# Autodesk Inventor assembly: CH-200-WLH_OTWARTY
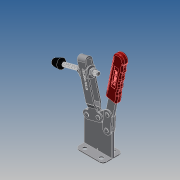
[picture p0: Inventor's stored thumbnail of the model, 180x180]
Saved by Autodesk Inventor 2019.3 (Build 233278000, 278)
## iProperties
Company: Î¢ÈíÖÐ¹ú
Created: 2011-05
Part Number: CH-200-WLH_OTWARTY
Material: Ogólny
Description: STEP AP203
Document SubType Name: Assembly
Designer: CADENGINEERING4
Sending System: SolidWorks 2010
Preprocessor: SwSTEP 2.0
Title: CH-200-WLH.STEP
Author: Î¢ÈíÓÃ»§
Revision Number: ÈÎºÎ
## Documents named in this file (10)
- E:\STRONA\Horizontal toggle clamp\CH-200-WLH\CH-200-WLH_OTWARTY.iam
- E:\STRONA\Horizontal toggle clamp\CH-200-WLH\FW380.ipt
- E:\STRONA\Horizontal toggle clamp\CH-200-WLH\200-W-05.ipt
- E:\STRONA\Horizontal toggle clamp\CH-200-WLH\38312-01.ipt
- E:\STRONA\Horizontal toggle clamp\CH-200-WLH\200-W-04.ipt
- E:\STRONA\Horizontal toggle clamp\CH-200-WLH\200-WLH-01.ipt
- E:\STRONA\Horizontal toggle clamp\CH-200-WLH\200-W-03.ipt
- E:\STRONA\Horizontal toggle clamp\CH-200-WLH\200-WLH-02.ipt
- E:\STRONA\Horizontal toggle clamp\CH-200-WLH\200-W-06.ipt
- E:\STRONA\Horizontal toggle clamp\CH-200-WLH\38412.ipt
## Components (15 placed, 15 different names)
1. FW380_1 — Zestawiające:3, Zestawiające:4, Równoległe:2, Zestawiające:7, Zestawiające:8, Równoległe:3
2. 200-W-05_2 — Zestawiające:14, Zestawiające:16, Zestawiające:28
3. 200-W-05_3 — Zestawiające:26, Zestawiające:27
4. 38312-01_4 — Zestawiające:4, Równoległe:1, Zestawiające:7
5. 200-W-04_5 — Zestawiające:20, Zestawiające:22, Zestawiające:23, Zestawiające:24, Zestawiające:25
6. 200-WLH-01_6 — Zestawiające:19, Zestawiające:20, Zestawiające:21, Zestawiające:22, Zestawiające:28, Zestawiające:29, Przejściowe:1
7. 200-W-03_7 — Zestawiające:11, Zestawiające:17, Zestawiające:18, Zestawiające:30, Zestawiające:31, Zestawiające:32, Przejściowe:1
8. 200-W-04_8 — Zestawiające:19, Zestawiające:21, Zestawiające:23, Zestawiające:26, Zestawiające:27
9. FW380_9 — Zestawiające:2, Równoległe:2, Zestawiające:6, Zestawiające:9
10. 200-WLH-02_10 — Zestawiające:5, Zestawiające:8, Zestawiające:9, Równoległe:3, Zestawiające:13, Zestawiające:14, Zestawiające:15, Zestawiające:16, Zestawiające:29, Zestawiające:30
11. 200-W-05_11 — Zestawiające:24, Zestawiające:25, Zestawiające:32
12. 38312-01_12 — Zestawiające:1, Zestawiające:6
13. 200-W-06_13 — Zestawiające:11, Zestawiające:17, Zestawiające:18
14. 38412_14 — Zestawiające:1, Zestawiające:2, Zestawiające:3, Równoległe:1, Zestawiające:5
15. 200-W-05_15 — Zestawiające:13, Zestawiające:15, Zestawiające:31
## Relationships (34: Mate 30, Flush 3, Transitional 1)
- Zestawiające:1 [Mate]: 38312-01_12 ↔ 38412_14
- Zestawiające:2 [Mate]: FW380_9 ↔ 38412_14
- Zestawiające:3 [Mate]: FW380_1 ↔ 38412_14
- Zestawiające:4 [Mate]: FW380_1 ↔ 38312-01_4
- Równoległe:1 [Flush]: 38312-01_4 ↔ 38412_14
- Równoległe:2 [Flush]: FW380_1 ↔ FW380_9
- Zestawiające:5 [Mate]: 200-WLH-02_10 ↔ 38412_14
- Zestawiające:6 [Mate]: FW380_9 ↔ 38312-01_12
- Zestawiające:7 [Mate]: FW380_1 ↔ 38312-01_4
- Zestawiające:8 [Mate]: FW380_1 ↔ 200-WLH-02_10
- Zestawiające:9 [Mate]: FW380_9 ↔ 200-WLH-02_10
- Równoległe:3 [Flush]: FW380_1 ↔ 200-WLH-02_10
- Zestawiające:11 [Mate]: 200-W-03_7 ↔ 200-W-06_13
- Zestawiające:13 [Mate]: 200-WLH-02_10 ↔ 200-W-05_15
- Zestawiające:14 [Mate]: 200-W-05_2 ↔ 200-WLH-02_10
- Zestawiające:15 [Mate]: 200-WLH-02_10 ↔ 200-W-05_15
- Zestawiające:16 [Mate]: 200-W-05_2 ↔ 200-WLH-02_10
- Zestawiające:17 [Mate]: 200-W-03_7 ↔ 200-W-06_13
- Zestawiające:18 [Mate]: 200-W-03_7 ↔ 200-W-06_13
- Zestawiające:19 [Mate]: 200-WLH-01_6 ↔ 200-W-04_8
- Zestawiające:20 [Mate]: 200-W-04_5 ↔ 200-WLH-01_6
- Zestawiające:21 [Mate]: 200-WLH-01_6 ↔ 200-W-04_8
- Zestawiające:22 [Mate]: 200-W-04_5 ↔ 200-WLH-01_6
- Zestawiające:23 [Mate]: 200-W-04_5 ↔ 200-W-04_8
- Zestawiające:24 [Mate]: 200-W-04_5 ↔ 200-W-05_11
- Zestawiające:25 [Mate]: 200-W-04_5 ↔ 200-W-05_11
- Zestawiające:26 [Mate]: 200-W-05_3 ↔ 200-W-04_8
- Zestawiające:27 [Mate]: 200-W-05_3 ↔ 200-W-04_8
- Zestawiające:28 [Mate]: 200-W-05_2 ↔ 200-WLH-01_6
- Zestawiające:29 [Mate]: 200-WLH-01_6 ↔ 200-WLH-02_10
- Zestawiające:30 [Mate]: 200-W-03_7 ↔ 200-WLH-02_10
- Zestawiające:31 [Mate]: 200-W-03_7 ↔ 200-W-05_15
- Zestawiające:32 [Mate]: 200-W-03_7 ↔ 200-W-05_11
- Przejściowe:1 [Transitional]: 200-WLH-01_6 ↔ 200-W-03_7
